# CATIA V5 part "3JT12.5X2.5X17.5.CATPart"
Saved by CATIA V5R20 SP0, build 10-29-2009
Part number: 3JT12.5X2.5X17.5
Revision: ANY
Definition: UNKNOWN
Nomenclature: 3JT12.5X2.5X17.5
Source: Unknown
Bounding box of the stored display mesh (mm): x -8.75 to 8.75, y -1.25 to 1.25, z -8.75 to 8.75
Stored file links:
  C:\Users\Utente\Desktop\IO LAVORO\3D X SITO CF\CUMSA\3D files PW\pw101830\pw101830_ejection\3JT12.5X2.5X17.5.CATPart
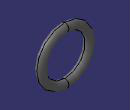
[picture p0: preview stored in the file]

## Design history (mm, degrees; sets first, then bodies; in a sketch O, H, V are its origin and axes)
Body1 "Revolución1" (main body)
  Solid1: solid without history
